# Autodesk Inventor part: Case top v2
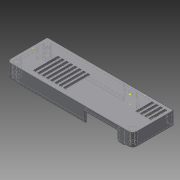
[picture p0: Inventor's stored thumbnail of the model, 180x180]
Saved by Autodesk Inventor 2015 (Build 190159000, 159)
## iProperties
Created: 2018-08
Part Number: Case top v2
Material: Generic
Document SubType Name: Modeling
Designer: Toby
Density: 1 g/cm^3
Appearance: Default
Author: Toby
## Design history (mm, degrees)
sketch "Sketch1"
  geometry: L1 (-84.862, 14.269)-(26.138, 14.269); L2 (26.138, 14.269)-(26.138, -23.731); L3 (26.138, -23.731)-(-84.862, -23.731); L4 (-84.862, -23.731)-(-84.862, 14.269); 1 further point
  constraints: 8 end point, 2 parallel, 1 horizontal, 1 perpendicular
  dimensions: "d0" = 38 distance between parallel lines of L3 L1; "d1" = 111 distance of L1.start L1.end
extrude "Extrusion1" new body sketch "Sketch1" distance "d2" = 1; taper "d3" = 0 deg
sketch "Sketch2"
  geometry: L1 (-84.862, 14.269)-(26.138, 14.269); L2 (26.138, 14.269)-(26.138, -23.731); L3 (26.138, -23.731)-(-84.862, -23.731); L4 (-84.862, -23.731)-(-84.862, 14.269); L5 (-83.862, 13.269)-(25.138, 13.269); L6 (25.138, 13.269)-(25.138, -22.731); L7 (25.138, -22.731)-(-83.862, -22.731); L8 (-83.862, -22.731)-(-83.862, 13.269); 1 further point
  constraints: 16 end point, 4 parallel, 2 horizontal, 2 perpendicular
  dimensions: "d4" = 1 distance between parallel lines of L5 L1; "d5" = 1 distance between parallel lines of L3 L7; "d6" = 1 distance between parallel lines of L4 L8; "d7" = 1 distance between parallel lines of L2 L6
extrude "Extrusion2" join sketch "Sketch2" distance "d8" = 7; taper "d9" = 0 deg
sketch "Sketch3"
  geometry: L1 (25.138, -22.731)-(25.138, 13.269) reference; L2 (25.138, -22.731)-(-83.862, -22.731) reference; C1 r 3 at (21.138, -18.731); 1 further point
  constraints: 1 centre point
  dimensions: "d10" = 6 diameter of C1; "d11" = 4 distance from line of L1 C1.centre; "d12" = 4 distance from line of L2 C1.centre
extrude "Extrusion3" join sketch "Sketch3" distance "d13" = 7; taper "d14" = 0 deg
sketch "Sketch4"
  geometry: C1 r 3 at (0, 0) reference; 2 further points
  constraints: 1 coincident
hole "Hole1" sketch "Sketch4" at (0, 0) diameter "d15" = 3; stored, may be unused: countersink angle "d19" = 90 deg, drill point angle "d21" = 118 deg; dims "d16" = 6, "d17" = 4, "d18" = 2, "d20" = 6
sketch "Sketch5"
  geometry: L1 (4, -4)-(0, -4); L2 (0, -4)-(0, -1.5); L3 (0, -1.5)-(4, -1.5); L4 (4, -1.5)-(4, -4); L5 (4, 32)-(4, -4) reference; L6 (4, 3)-(1.5, 3); L7 (1.5, 3)-(1.5, -1.5); L8 (1.5, -1.5)-(4, -1.5); L9 (4, -1.5)-(4, 3); 2 further points
  constraints: 16 end point, 4 parallel, 2 horizontal, 2 perpendicular, 2 point on line, 1 vertical alignment, 1 other
extrude "Extrusion4" join sketch "Sketch5" distance "d22" = 7; taper "d23" = 0 deg
sketch "Sketch6"
  geometry: L1 (25.138, 13.269)-(25.138, -15.731) reference; L2 (25.138, -0.731)-(13.138, -0.731); L3 (13.138, -0.731)-(13.138, -3.731); L4 (13.138, -3.731)-(25.138, -3.731); L5 (25.138, -3.731)-(25.138, -0.731); L6 (-83.862, 13.269)-(25.138, 13.269) reference; 1 further point
  constraints: 8 end point, 2 parallel, 1 horizontal, 1 perpendicular, 1 point on line
  dimensions: "d24" = 3 distance between parallel lines of L4 L2; "d25" = 14 distance between parallel lines of L6 L2; "d26" = 12 distance between parallel lines of L1 L3
extrude "Extrusion5" join sketch "Sketch6" distance "d27" = 4; taper "d28" = 0 deg
sketch "Sketch7"
  geometry: L1 (111, 0)-(0, 0) reference; L2 (0, -8)-(111, -8) reference; L3 (109, 0)-(94, 0); L4 (94, 0)-(94, -8); L5 (94, -8)-(109, -8); L6 (109, -8)-(109, 0); L7 (110, -1)-(110, -5) reference; 1 further point
  constraints: 8 end point, 2 parallel, 2 point on line, 1 horizontal, 1 perpendicular
  dimensions: "d29" = 1 distance between parallel lines of L7 L6; "d30" = 15 distance between parallel lines of L4 L6
extrude "Extrusion6" cut sketch "Sketch7" distance "d31" = 1; taper "d32" = 0 deg
sketch "Sketch8"
  geometry: 1 further point
sketch "Sketch9"
  geometry: L1 (-5, 20)-(-1, 20) reference; L2 (-1, 8)-(-1, 20) reference; L3 (-2.5, 20)-(-1, 20); L4 (-1, 20)-(-1, 14); L5 (-1, 14)-(-2.5, 14); L6 (-2.5, 14)-(-2.5, 20); 1 further point
  constraints: 8 end point, 2 parallel, 1 horizontal, 1 midpoint, 1 perpendicular, 1 point on line
  dimensions: "d33" = 6 distance of L5.end L3.start; "d34" = 1.5 distance between parallel lines of L2 L6
extrude "Extrusion7" cut sketch "Sketch9" distance "d35" = 1; taper "d36" = 0 deg
sketch "Sketch10"
  geometry: L1 (-84.862, 14.269)-(-89.862, 14.269); L2 (-89.862, 14.269)-(-89.862, -23.731); L3 (-89.862, -23.731)-(-84.862, -23.731); L4 (-84.862, -23.731)-(-84.862, 14.269); L5 (-84.862, -23.731)-(26.138, -23.731) reference; 1 further point
  constraints: 8 end point, 2 parallel, 1 collinear, 1 horizontal, 1 perpendicular
  dimensions: "d37" = 5 distance of L3.end L2.end
extrude "Extrusion8" join sketch "Sketch10" distance "d38" = 1; taper "d39" = 0 deg
sketch "Sketch11"
  geometry: L1 (-83.862, 13.269)-(-83.862, -22.731) reference; L2 (-89.862, 14.269)-(-83.862, 14.269); L3 (-83.862, 14.269)-(-83.862, 8.269); L4 (-83.862, 8.269)-(-89.862, 8.269); L5 (-89.862, 8.269)-(-89.862, 14.269); L6 (-89.862, -23.731)-(-83.862, -23.731); L7 (-83.862, -23.731)-(-83.862, -17.731); L8 (-83.862, -17.731)-(-89.862, -17.731); L9 (-89.862, -17.731)-(-89.862, -23.731); L10 (-89.862, 8.269)-(-88.862, 8.269); L11 (-88.862, 8.269)-(-88.862, -17.731); L12 (-88.862, -17.731)-(-89.862, -17.731); L13 (-89.862, -17.731)-(-89.862, 8.269); 1 further point
  constraints: 24 end point, 6 parallel, 3 horizontal, 3 perpendicular, 3 point on line
  dimensions: "d40" = 6 distance of L2.end L3.end; "d41" = 6 distance of L7.end L6.end; "d42" = 1 distance between parallel lines of L13 L11
extrude "Extrusion9" join sketch "Sketch11" distance "d43" = 7; taper "d44" = 0 deg
sketch "Sketch12"
  geometry: L1 (-84.862, 8.269)-(-83.862, 8.269); L2 (-83.862, 8.269)-(-83.862, -17.731); L3 (-83.862, -17.731)-(-84.862, -17.731); L4 (-84.862, -17.731)-(-84.862, 8.269); L5 (-84.862, -17.731)-(-88.862, -17.731) reference; L6 (-83.862, -22.731)-(-83.862, 13.269) reference; 1 further point
  constraints: 8 end point, 2 collinear, 2 parallel, 1 horizontal, 1 perpendicular
extrude "Extrusion10" cut sketch "Sketch12" distance "d45" = 7; taper "d46" = 0 deg
sketch "Sketch13"
  geometry: L1 (-88.862, 8.269)-(-83.862, 8.269) reference; L2 (-83.862, 8.269)-(-83.862, 13.269) reference; L3 (-83.862, -17.731)-(-88.862, -17.731) reference; 3 further points
  dimensions: "d47" = 3 distance from line of L1 point (-86.862, 11.269); "d48" = 3 distance from line of L2 point (-86.862, 11.269); "d49" = 3 distance from line of L3 point (-86.862, -20.731)
hole "Hole2" sketch "Sketch13" at (-86.862, 11.269), (-86.862, -20.731) diameter "d50" = 3; stored, may be unused: countersink angle "d54" = 90 deg, drill point angle "d56" = 118 deg; dims "d51" = 6, "d52" = 4, "d53" = 2, "d55" = 6
fillet "Fillet1" dims "d57" = 4
fillet "Fillet2" dims "d58" = 2
sketch "Sketch15"
  geometry: L1 (-85.862, -23.731)-(22.138, -23.731) reference; L2 (-89.862, 14.269)-(-83.862, 14.269); L3 (-83.862, 14.269)-(-83.862, -23.731); L4 (-83.862, -23.731)-(-89.862, -23.731); L5 (-89.862, -23.731)-(-89.862, 14.269); L6 (-83.862, 10.269)-(-83.862, 13.269) reference; 1 further point
  constraints: 8 end point, 2 parallel, 1 collinear, 1 horizontal, 1 perpendicular, 1 point on line
extrude "Extrusion11" cut sketch "Sketch15" distance "d59" = 10; taper "d60" = 0 deg
sketch "Sketch16"
  geometry: L1 (-83.862, 14.269)-(-91.862, 14.269); L2 (-91.862, 14.269)-(-91.862, -23.731); L3 (-91.862, -23.731)-(-83.862, -23.731); L4 (-83.862, -23.731)-(-83.862, 14.269); L5 (-83.862, -23.731)-(22.138, -23.731) reference; 1 further point
  constraints: 8 end point, 2 parallel, 1 collinear, 1 horizontal, 1 perpendicular
  dimensions: "d61" = 8 distance between parallel lines of L4 L2
extrude "Extrusion12" join sketch "Sketch16" distance "d62" = 1; taper "d63" = 0 deg
sketch "Sketch17"
  geometry: L1 (22.138, -23.731)-(-91.862, -23.731) reference; L2 (-91.862, 14.269)-(-90.862, 14.269); L3 (-90.862, 14.269)-(-90.862, -23.731); L4 (-90.862, -23.731)-(-91.862, -23.731); L5 (-91.862, -23.731)-(-91.862, 14.269); L6 (-90.862, 14.269)-(-83.862, 14.269); L7 (-83.862, 14.269)-(-83.862, 13.269); L8 (-83.862, 13.269)-(-90.862, 13.269); L9 (-90.862, 13.269)-(-90.862, 14.269); L10 (-83.862, -22.731)-(-90.862, -22.731); L11 (-90.862, -22.731)-(-90.862, -23.731); L12 (-90.862, -23.731)-(-83.862, -23.731); L13 (-83.862, -23.731)-(-83.862, -22.731); 1 further point
  constraints: 24 end point, 6 parallel, 3 horizontal, 3 perpendicular, 1 point on line
  dimensions: "d64" = 1 distance of L3.end L4.end
extrude "Extrusion13" join sketch "Sketch17" distance "d65" = 7; taper "d66" = 0 deg
sketch "Sketch18"
  geometry: 1 further point
sketch "Sketch19"
  geometry: 1 further point
sketch "Sketch20" dims "d67" = 6
  geometry: L1 (-91.862, 14.269)-(-91.862, -23.731) reference; L2 (9.138, 14.269)-(-91.862, 14.269) reference; L3 (-91.862, -23.731)-(22.138, -23.731) reference; L4 (-90.862, 13.269)-(-90.862, -22.731) reference; L5 (21.138, -22.731)-(-90.862, -22.731) reference; L6 (-90.862, -15.731)-(-86.862, -15.731); L7 (-86.862, -15.731)-(-86.862, -22.731); L8 (-86.862, -22.731)-(-90.862, -22.731); L9 (-90.862, -22.731)-(-90.862, -15.731); L10 (-86.862, -18.731)-(-83.862, -18.731); L11 (-83.862, -18.731)-(-83.862, -22.731); L12 (-83.862, -22.731)-(-86.862, -22.731); L13 (-86.862, -22.731)-(-86.862, -18.731); L14 (-86.862, 9.269)-(-83.862, 9.269); L15 (-83.862, 9.269)-(-83.862, 13.269); L16 (-83.862, 13.269)-(-86.862, 13.269); L17 (-86.862, 13.269)-(-86.862, 9.269); L18 (-90.862, 13.269)-(-86.862, 13.269); L19 (-86.862, 13.269)-(-86.862, 6.269); L20 (-86.862, 6.269)-(-90.862, 6.269); L21 (-90.862, 6.269)-(-90.862, 13.269); C1 r 3 at (-86.862, -18.731); 1 further point
  constraints: 32 end point, 8 parallel, 4 horizontal, 4 perpendicular, 4 point on line, 1 centre point, 1 vertical alignment, 2 other
  dimensions: "d68" = 5 distance from line of L1 L14.start; "d69" = 5 distance from line of L2 L14.start; "d70" = 6 diameter of C1; "d71" = 5 distance from line of L1 L10.start; "d72" = 5 distance from line of L3 L10.start
extrude "Extrusion14" join sketch "Sketch20" distance "d73" = 7; taper "d74" = 0 deg
sketch "Sketch21"
  geometry: L1 (-91.862, 14.269)-(9.138, 14.269) reference; L2 (-91.862, -23.731)-(-91.862, 14.269) reference; L3 (-91.862, -23.731)-(22.138, -23.731) reference; 3 further points
  dimensions: "d75" = 5 distance from line of L1 point (-86.862, 9.269); "d76" = 5 distance from line of L2 point (-86.862, 9.269); "d77" = 5 distance from line of L2 point (-86.862, -18.731); "d78" = 5 distance from line of L3 point (-86.862, -18.731)
hole "Hole3" sketch "Sketch21" at (-86.862, 9.269), (-86.862, -18.731) diameter "d79" = 3; stored, may be unused: countersink angle "d83" = 90 deg, drill point angle "d85" = 118 deg; dims "d80" = 6, "d81" = 4, "d82" = 2, "d84" = 6
fillet "Fillet3" dims "d86" = 4
sketch "Sketch22"
  geometry: L1 (26.138, -23.731)-(-91.862, -23.731); L2 (-91.862, -23.731)-(-91.862, 14.269); L3 (-91.862, 14.269)-(26.138, 14.269); L4 (26.138, 14.269)-(26.138, -23.731); L5 (-87.862, -23.731)-(22.138, -23.731) reference; L6 (26.138, -19.731)-(26.138, 14.269) reference; 1 further point
  constraints: 8 end point, 2 collinear, 2 parallel, 1 horizontal, 1 perpendicular
extrude "Extrusion15" cut sketch "Sketch22" distance "d87" = 7; taper "d88" = 0 deg
sketch "Sketch23"
  geometry: L1 (24.138, 14.269)-(9.138, 14.269); L2 (9.138, 14.269)-(9.138, 13.269); L3 (9.138, 13.269)-(24.138, 13.269); L4 (24.138, 13.269)-(24.138, 14.269); 1 further point
  constraints: 8 end point, 2 parallel, 1 horizontal, 1 perpendicular
extrude "Extrusion16" join sketch "Sketch23" distance "d89" = 1; taper "d90" = 0 deg
sketch "Sketch24"
  geometry: L1 (91.862, 14.269)-(-26.138, 14.269); L2 (-26.138, 14.269)-(-26.138, -23.731); L3 (-26.138, -23.731)-(91.862, -23.731); L4 (91.862, -23.731)-(91.862, 14.269); L5 (-22.138, -23.731)-(87.862, -23.731) reference; L6 (-26.138, 14.269)-(-26.138, -19.731) reference; 1 further point
  constraints: 8 end point, 2 collinear, 2 parallel, 1 horizontal, 1 perpendicular
extrude "Extrusion17" join sketch "Sketch24" distance "d91" = 11; taper "d92" = 0 deg
fillet "Fillet4" dims "d93" = 4
sketch "Sketch25"
  geometry: L1 (90.862, 13.269)-(-25.138, 13.269); L2 (-25.138, 13.269)-(-25.138, -19.731); L3 (-25.138, -19.731)-(90.862, -19.731); L4 (90.862, -19.731)-(90.862, 13.269); L5 (-22.138, -23.731)-(87.862, -23.731) reference; L6 (91.862, -19.731)-(91.862, 14.269) reference; L7 (-26.138, 14.269)-(-26.138, -19.731) reference; L8 (91.862, 14.269)-(-26.138, 14.269) reference; 1 further point
  constraints: 8 end point, 2 parallel, 1 horizontal, 1 perpendicular
  dimensions: "d94" = 4 distance between parallel lines of L5 L3; "d95" = 1 distance between parallel lines of L6 L4; "d96" = 1 distance between parallel lines of L7 L2; "d97" = 1 distance between parallel lines of L8 L1
extrude "Extrusion18" cut sketch "Sketch25" distance "d98" = 11; taper "d99" = 0 deg
sketch "Sketch26"
  geometry: L1 (87.862, -19.731)-(-22.138, -19.731); L2 (-22.138, -19.731)-(-22.138, -22.731); L3 (-22.138, -22.731)-(87.862, -22.731); L4 (87.862, -22.731)-(87.862, -19.731); L5 (-26.138, 14.269)-(-26.138, -19.731) reference; A1 r 4 centre (87.862, -19.731) between (87.862, -23.731) and (91.862, -19.731) reference; 1 further point
  constraints: 8 end point, 2 parallel, 1 horizontal, 1 perpendicular
  dimensions: "d100" = 3 distance of L2.end L1.end; "d101" = 4 distance between parallel lines of L5 L2
extrude "Extrusion19" cut sketch "Sketch26" distance "d102" = 11; taper "d103" = 0 deg
sketch "Sketch27"
  geometry: L1 (-22.138, -23.731)-(87.862, -23.731) reference; L2 (91.862, -19.731)-(91.862, 14.269) reference; L3 (-26.138, 14.269)-(-26.138, -19.731) reference; C1 r 3 at (86.862, -18.731); C2 r 3 at (-21.138, -18.731); 1 further point
  constraints: 2 centre point
  dimensions: "d104" = 6 diameter of C1; "d105" = 6 diameter of C2; "d106" = 5 distance from line of L1 C1.centre; "d107" = 5 distance from line of L2 C1.centre; "d108" = 5 distance from line of L1 C2.centre; "d109" = 5 distance from line of L3 C2.centre
extrude "Extrusion20" join sketch "Sketch27" distance "d110" = 11; taper "d111" = 0 deg
sketch "Sketch28"
  geometry: A1 r 3 centre (86.862, -18.731) between (89.69, -19.731) and (87.862, -21.56) reference; A2 r 3 centre (-21.138, -18.731) between (-22.138, -21.56) and (-23.967, -19.731) reference; 3 further points
  constraints: 2 coincident
hole "Hole4" sketch "Sketch28" at (86.862, -18.731), (-21.138, -18.731) diameter "d112" = 3; stored, may be unused: countersink angle "d116" = 90 deg, drill point angle "d118" = 118 deg; dims "d113" = 6, "d114" = 4, "d115" = 2, "d117" = 12
sketch "Sketch29"
  geometry: C1 r 1.5 at (21.138, -18.731) reference; C2 r 1.5 at (-86.862, -18.731) reference; 3 further points
  constraints: 2 coincident
hole "Hole5" sketch "Sketch29" at (21.138, -18.731), (-86.862, -18.731) diameter "d119" = 3; stored, may be unused: countersink angle "d123" = 90 deg, drill point angle "d125" = 118 deg; dims "d120" = 6, "d121" = 6, "d122" = 2, "d124" = 12
sketch "Sketch30"
  geometry: L1 (91.862, -19.731)-(91.862, 14.269) reference; L2 (91.862, 14.269)-(-26.138, 14.269) reference; L3 (86.862, 9.269)-(90.862, 9.269); L4 (90.862, 9.269)-(90.862, 13.269); L5 (90.862, 13.269)-(86.862, 13.269); L6 (86.862, 13.269)-(86.862, 9.269); C1 r 3 at (86.862, 9.269); 1 further point
  constraints: 8 end point, 2 parallel, 1 centre point, 1 horizontal, 1 perpendicular
  dimensions: "d126" = 6 diameter of C1; "d127" = 5 distance from line of L1 L3.start; "d128" = 5 distance from line of L2 L3.start
extrude "Extrusion21" join sketch "Sketch30" distance "d129" = 11; taper "d130" = 0 deg
sketch "Sketch31"
  geometry: A1 r 3 centre (86.862, 9.269) between (86.862, 12.269) and (89.862, 9.269) reference; 2 further points
  constraints: 1 coincident
hole "Hole6" sketch "Sketch31" at (86.862, 9.269) diameter "d131" = 3; stored, may be unused: countersink angle "d135" = 90 deg, drill point angle "d137" = 118 deg; dims "d132" = 6, "d133" = 6, "d134" = 2, "d136" = 12
sketch "Sketch32"
  geometry: C1 r 1.5 at (-86.862, 9.269) reference; 2 further points
  constraints: 1 coincident
hole "Hole7" sketch "Sketch32" at (-86.862, 9.269) diameter "d138" = 3; stored, may be unused: countersink angle "d142" = 90 deg, drill point angle "d144" = 118 deg; dims "d139" = 6, "d140" = 6, "d141" = 2, "d143" = 12
sketch "Sketch33"
  geometry: 1 further point
sketch "Sketch34"
  geometry: L1 (113, -12)-(1, -12) reference; L2 (69, -12)-(100, -12); L3 (100, -12)-(100, -4); L4 (100, -4)-(69, -4); L5 (69, -4)-(69, -12); L6 (114, -12)-(114, 0) reference; 1 further point
  constraints: 8 end point, 2 parallel, 1 horizontal, 1 perpendicular, 1 point on line
  dimensions: "d145" = 8 distance between parallel lines of L1 L4; "d146" = 14 distance between parallel lines of L6 L3; "d147" = 45 distance between parallel lines of L6 L5
extrude "Extrusion22" cut sketch "Sketch34" distance "d148" = 1; taper "d149" = 0 deg
sketch "Sketch35"
  geometry: L1 (111.5, 12)-(114.5, 12) reference; L2 (113, 12)-(104, 12); L3 (104, 12)-(104, 7); L4 (104, 7)-(113, 7); L5 (113, 7)-(113, 12); L6 (118, 0)-(118, 12) reference; L7 (0, 12)-(118, 12) reference; 1 further point
  constraints: 8 end point, 2 parallel, 1 horizontal, 1 midpoint, 1 perpendicular
  dimensions: "d150" = 14 distance between parallel lines of L6 L3; "d151" = 5 distance between parallel lines of L7 L4
extrude "Extrusion23" cut sketch "Sketch35" distance "d152" = 1; taper "d153" = 0 deg
sketch "Sketch36"
  geometry: L1 (0, 12)-(104, 12) reference; L2 (85, 12)-(73, 12); L3 (73, 12)-(73, 5); L4 (73, 5)-(85, 5); L5 (85, 5)-(85, 12); L6 (118, 0)-(118, 12) reference; 1 further point
  constraints: 8 end point, 2 parallel, 1 horizontal, 1 perpendicular, 1 point on line
  dimensions: "d154" = 33 distance between parallel lines of L6 L5; "d155" = 45 distance between parallel lines of L6 L3; "d156" = 7 distance between parallel lines of L1 L4
extrude "Extrusion24" cut sketch "Sketch36" distance "d157" = 1; taper "d158" = 0 deg
sketch "Sketch37"
  geometry: L1 (-12.138, 13.269)-(6.862, 13.269); L2 (6.862, 13.269)-(6.862, 12.669); L3 (6.862, 12.669)-(-12.138, 12.669); L4 (-12.138, 12.669)-(-12.138, 13.269); L5 (6.862, 13.269)-(6.862, 14.269) reference; L6 (18.862, 13.269)-(86.862, 13.269); L7 (86.862, 13.269)-(86.862, 12.669); L8 (86.862, 12.669)-(18.862, 12.669); L9 (18.862, 12.669)-(18.862, 13.269); L10 (86.862, 13.269)-(86.862, 12.269) reference; 1 further point
  constraints: 16 end point, 4 parallel, 2 collinear, 2 horizontal, 2 perpendicular
  dimensions: "d159" = 0.6 distance between parallel lines of L1 L3; "d160" = 0.6 distance between parallel lines of L8 L6
extrude "Extrusion25" join sketch "Sketch37" distance "d161" = 13; taper "d162" = 0 deg
sketch "Sketch38"
  geometry: L1 (-12, 0)-(-12, 33) reference; L2 (-12, 24)-(-5, 24); L3 (-5, 24)-(-5, 8); L4 (-5, 8)-(-12, 8); L5 (-12, 8)-(-12, 24); L6 (-12, 34)-(0, 34) reference; 1 further point
  constraints: 8 end point, 2 parallel, 1 horizontal, 1 perpendicular, 1 point on line
  dimensions: "d163" = 10 distance between parallel lines of L6 L2; "d164" = 26 distance between parallel lines of L6 L4; "d165" = 7 distance between parallel lines of L1 L3
extrude "Extrusion26" cut sketch "Sketch38" distance "d166" = 13; taper "d167" = 0 deg
sketch "Sketch39"
  geometry: L1 (90.862, 9.269)-(90.262, 9.269); L2 (90.262, 9.269)-(90.262, 4.269); L3 (90.262, 4.269)-(90.862, 4.269); L4 (90.862, 4.269)-(90.862, 9.269); L5 (90.862, -19.731)-(89.69, -19.731) reference; L6 (90.862, -11.731)-(90.262, -11.731); L7 (90.262, -11.731)-(90.262, -19.731); L8 (90.262, -19.731)-(90.862, -19.731); L9 (90.862, -19.731)-(90.862, -11.731); L10 (91.862, 4.269)-(90.862, 4.269) reference; 1 further point
  constraints: 16 end point, 4 parallel, 2 horizontal, 2 perpendicular, 1 collinear, 1 point on line
  dimensions: "d168" = 0.6 distance of L3.end L2.end; "d169" = 0.6 distance of L8.end L7.end
extrude "Extrusion27" join sketch "Sketch39" distance "d170" = 13; taper "d171" = 0 deg
sketch "Sketch40"
  geometry: L1 (18.862, 13.269)-(86.862, 13.269) reference; L2 (90.862, 9.269)-(90.862, 4.269) reference; L3 (83.862, 13.269)-(90.862, 13.269); L4 (90.862, 13.269)-(90.862, 6.269); L5 (90.862, 6.269)-(83.862, 6.269); L6 (83.862, 6.269)-(83.862, 13.269); 1 further point
  constraints: 8 end point, 2 parallel, 2 point on line, 1 horizontal, 1 perpendicular
extrude "Extrusion28" cut sketch "Sketch40" distance "d172" = 3; taper "d173" = 0 deg
sketch "Sketch41"
  geometry: L1 (86.862, -15.731)-(90.862, -15.731); L2 (90.862, -15.731)-(90.862, -19.731); L3 (90.862, -19.731)-(86.862, -19.731); L4 (86.862, -19.731)-(86.862, -15.731); A1 r 3 centre (86.862, -18.731) between (89.69, -19.731) and (87.862, -21.56) reference; 1 further point
  constraints: 8 end point, 2 parallel, 1 horizontal, 1 perpendicular, 1 point on circle
extrude "Extrusion29" cut sketch "Sketch41" distance "d174" = 2; taper "d175" = 0 deg
sketch "Sketch42"
  geometry: L1 (87.862, -22.731)-(-22.138, -22.731) reference; L2 (-17.138, -22.131)-(-12.138, -22.131); L3 (-12.138, -22.131)-(-12.138, -22.731); L4 (-12.138, -22.731)-(-17.138, -22.731); L5 (-17.138, -22.731)-(-17.138, -22.131); L6 (18.862, -22.731)-(83.862, -22.731); L7 (83.862, -22.731)-(83.862, -22.131); L8 (83.862, -22.131)-(18.862, -22.131); L9 (18.862, -22.131)-(18.862, -22.731); L10 (-12.138, -23.731)-(-12.138, -22.731) reference; 1 further point
  constraints: 16 end point, 4 parallel, 2 horizontal, 2 perpendicular, 1 collinear, 1 point on line
  dimensions: "d176" = 0.6 distance of L7.end L6.end; "d177" = 0.6 distance between parallel lines of L1 L2; "d178" = 5 distance of L2.start L2.end
extrude "Extrusion30" join sketch "Sketch42" distance "d179" = 13; taper "d180" = 0 deg
chamfer "Chamfer1" distance "d181" = 1; stored, may be unused: second distance "d182" = 2, angle "d183" = 45 deg
sketch "Sketch43"
  geometry: L1 (18.862, 13.269)-(83.862, 13.269) reference; L2 (82.862, 13.269)-(83.862, 13.269); L3 (83.862, 13.269)-(83.862, -22.731); L4 (83.862, -22.731)-(82.862, -22.731); L5 (82.862, -22.731)-(82.862, 13.269); 1 further point
  constraints: 8 end point, 2 parallel, 1 horizontal, 1 perpendicular, 1 point on line
  dimensions: "d184" = 1 distance between parallel lines of L3 L5
extrude "Extrusion31" cut sketch "Sketch43" distance "d185" = 2; taper "d186" = 0 deg
sketch "Sketch44"
  geometry: L1 (21.138, 11.269)-(23.138, 11.269); L2 (23.138, 11.269)-(23.138, -3.731); L3 (23.138, -3.731)-(21.138, -3.731); L4 (21.138, -3.731)-(21.138, 11.269); L5 (26.138, 14.269)-(-91.862, 14.269) reference; L6 (26.138, 14.269)-(26.138, -19.731) reference; L7 (17.138, -3.731)-(17.138, 11.269); L8 (19.138, 11.269)-(19.138, -3.731); L9 (17.138, 11.269)-(19.138, 11.269); L10 (19.138, -3.731)-(17.138, -3.731); L11 (13.138, -3.731)-(13.138, 11.269); L12 (15.138, 11.269)-(15.138, -3.731); L13 (13.138, 11.269)-(15.138, 11.269); L14 (15.138, -3.731)-(13.138, -3.731); L15 (9.138, -3.731)-(9.138, 11.269); L16 (11.138, 11.269)-(11.138, -3.731); L17 (9.138, 11.269)-(11.138, 11.269); L18 (11.138, -3.731)-(9.138, -3.731); 3 further points
  constraints: 32 end point, 8 parallel, 4 horizontal, 4 perpendicular
  dimensions: "d187" = 2 distance between parallel lines of L2 L4; "d188" = 3 distance between parallel lines of L5 L1; "d189" = 3 distance between parallel lines of L6 L2; "d190" = 15 distance between parallel lines of L3 L1; "d191" = 2 distance from line of L4 point (19.138, 11.269); "d192" = 2 distance from line of L2 point (25.138, 11.269); "d193" = 2 distance between parallel lines of L8 L7; "d194" = 15 distance between parallel lines of L10 L9; "d195" = 2 distance between parallel lines of L12 L11; "d196" = 15 distance between parallel lines of L14 L13; "d197" = 2 distance between parallel lines of L16 L15; "d198" = 15 distance between parallel lines of L18 L17
extrude "Extrusion32" cut sketch "Sketch44" distance "d199" = 2; taper "d200" = 0 deg
sketch "Sketch45"
  geometry: L1 (-71.862, 4.269)-(-69.862, 4.269); L2 (-69.862, 4.269)-(-69.862, -18.731); L3 (-69.862, -18.731)-(-71.862, -18.731); L4 (-71.862, -18.731)-(-71.862, 4.269); L5 (-91.862, -19.731)-(-91.862, 14.269) reference; L6 (22.138, -23.731)-(-87.862, -23.731) reference; L7 (26.138, 14.269)-(-91.862, 14.269) reference; L8 (-67.862, -18.731)-(-67.862, 4.269); L9 (-67.862, 4.269)-(-65.862, 4.269); L10 (-65.862, 4.269)-(-65.862, -18.731); L11 (-65.862, -18.731)-(-67.862, -18.731); L12 (-63.862, -18.731)-(-63.862, 4.269); L13 (-63.862, 4.269)-(-61.862, 4.269); L14 (-61.862, 4.269)-(-61.862, -18.731); L15 (-61.862, -18.731)-(-63.862, -18.731); L16 (-59.862, -18.731)-(-59.862, 4.269); L17 (-59.862, 4.269)-(-57.862, 4.269); L18 (-57.862, 4.269)-(-57.862, -18.731); L19 (-57.862, -18.731)-(-59.862, -18.731); L20 (-55.862, -18.731)-(-55.862, 4.269); L21 (-55.862, 4.269)-(-53.862, 4.269); L22 (-53.862, 4.269)-(-53.862, -18.731); L23 (-53.862, -18.731)-(-55.862, -18.731); L24 (-51.862, -18.731)-(-51.862, 4.269); L25 (-51.862, 4.269)-(-49.862, 4.269); L26 (-49.862, 4.269)-(-49.862, -18.731); L27 (-49.862, -18.731)-(-51.862, -18.731); L28 (-47.862, -18.731)-(-47.862, 4.269); L29 (-47.862, 4.269)-(-45.862, 4.269); L30 (-45.862, 4.269)-(-45.862, -18.731); L31 (-45.862, -18.731)-(-47.862, -18.731); L32 (-43.862, -18.731)-(-43.862, 4.269); L33 (-43.862, 4.269)-(-41.862, 4.269); L34 (-41.862, 4.269)-(-41.862, -18.731); L35 (-41.862, -18.731)-(-43.862, -18.731); 4 further points
  constraints: 64 end point, 16 parallel, 8 horizontal, 8 perpendicular
  dimensions: "d201" = 20 distance from line of L5 point (-71.862, -19.57); "d202" = 50 distance from line of L5 point (-41.862, -19.731); "d203" = 20 distance between parallel lines of L5 L4; "d204" = 2 distance between parallel lines of L4 L2; "d205" = 5 distance between parallel lines of L6 L3; "d206" = 10 distance between parallel lines of L1 L7; "d207" = 2 distance from line of L4 point (-73.862, 4.269); "d208" = 2 distance between parallel lines of L8 L10; "d209" = 2 distance between parallel lines of L12 L14; "d210" = 2 distance between parallel lines of L16 L18; "d211" = 2 distance between parallel lines of L20 L22; "d212" = 2 distance between parallel lines of L24 L26; "d213" = 2 distance between parallel lines of L28 L30; "d214" = 2 distance between parallel lines of L32 L34
extrude "Extrusion33" cut sketch "Sketch45" distance "d215" = 2; taper "d216" = 0 deg
sketch "Sketch46"
  geometry: L1 (0, 2)-(19, 2) reference; L2 (19, 0)-(13, 0); L3 (13, 0)-(13, 2); L4 (13, 2)-(19, 2); L5 (19, 2)-(19, 0); 1 further point
  constraints: 8 end point, 2 parallel, 1 horizontal, 1 perpendicular, 1 point on line
  dimensions: "d217" = 6 distance between parallel lines of L5 L3
extrude "Extrusion34" cut sketch "Sketch46" distance "d218" = 2; taper "d219" = 0 deg
sketch "Sketch47"
  geometry: L1 (89.862, 9.269)-(89.862, -18.731) reference; L2 (90.862, 6.269)-(89.862, 6.269); L3 (89.862, 6.269)-(89.862, -15.731); L4 (89.862, -15.731)-(90.862, -15.731); L5 (90.862, -15.731)-(90.862, 6.269); 1 further point
  constraints: 8 end point, 2 parallel, 1 horizontal, 1 perpendicular, 1 point on line
extrude "Extrusion35" cut sketch "Sketch47" distance "d220" = 2; taper "d221" = 0 deg
sketch "Sketch48"
  geometry: C1 r 1.5 at (21.138, -18.731) reference; C2 r 3 at (21.138, -18.731); C3 r 1.5 at (-86.862, -18.731) reference; C4 r 3 at (-86.862, -18.731); C5 r 3 at (-86.862, 9.269) reference; C6 r 3 at (-86.862, 9.269); 1 further point
  constraints: 3 centre point, 3 coincident
  dimensions: "d222" = 6 diameter of C2; "d223" = 6 diameter of C4; "d224" = 6 diameter of C6
extrude "Extrusion36" join sketch "Sketch48" distance "d225" = 3; taper "d226" = 0 deg
body "Solid1"
